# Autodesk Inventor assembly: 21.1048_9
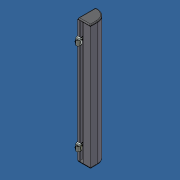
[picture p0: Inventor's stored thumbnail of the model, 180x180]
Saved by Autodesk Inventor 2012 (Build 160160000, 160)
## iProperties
Created: 2007-02
Part Number: 21.1048_9
Document SubType Name: Assembly
Designer: Andy Moles
Description: CLOSED PROT HANDLE FRONT MOUNT
Author: Andy Moles
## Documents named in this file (6)
- C:\Andys Backup Data\ANDY'S INVENTOR\INVENTOR LIBRARIES\PARTS LIBRARY\HANDLES LOCKS STOPS\21.1048_9 CLOSED PROT HANDLE FRONT.iam
- C:\Andys Backup Data\ANDY'S INVENTOR\INVENTOR LIBRARIES\PARTS LIBRARY\END CAPS\22.1054 END CAP FOR HANDLE PROFILE RIGHT GRAY.ipt
- C:\Andys Backup Data\ANDY'S INVENTOR\INVENTOR LIBRARIES\PARTS LIBRARY\END CAPS\22.1055 END CAP FOR HANDLE PROFILE LEFT GRAY.ipt
- C:\Andys Backup Data\ANDY'S INVENTOR\INVENTOR LIBRARIES\PARTS LIBRARY\HANDLES LOCKS STOPS\SUBCOMPONENTS\21.1048_8 HANDLE PROFILE.ipt
- C:\Andys Backup Data\ANDY'S INVENTOR\INVENTOR LIBRARIES\PARTS LIBRARY\FASTENING ELEMENTS\BUTTON HEAD FLANGE SCREWS\21.9966 M6X25 BUTTON HEAD FLANGE.ipt
- C:\Andys Backup Data\ANDY'S INVENTOR\INVENTOR LIBRARIES\PARTS LIBRARY\FASTENING ELEMENTS\NUTS\21.1330_2 M6 SQUARE NUT POS FXG.ipt
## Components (7 placed, 5 different names)
1. 21.1048_8 HANDLE PROFILE:1 — Flush:1, Mate:1, Flush:2, Mate:2, Mate:3, Flush:3, Mate:4, Mate:5, Flush:4, Insert:1, Insert:2, Mate:7, Mate:9, Angle:2
2. 22.1054 END CAP FOR HANDLE PROFILE RIGHT GRAY:1 — Mate:2, Mate:3, Flush:3, Angle:1
3. 22.1055 END CAP FOR HANDLE PROFILE LEFT GRAY:1 — Mate:4, Mate:5, Flush:4
4. 21.9966 M6X25 BUTTON HEAD FLANGE:1 — Insert:1, Mate:6
5. 21.9966 M6X25 BUTTON HEAD FLANGE:2 — Insert:2, Mate:8
6. 21.1330_2 M6 SQUARE NUT POS FXG:1 — Mate:6, Mate:7, Angle:1
7. 21.1330_2 M6 SQUARE NUT POS FXG:2 — Mate:8, Mate:9, Angle:2
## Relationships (17: Mate 9, Flush 4, Insert 2, Angle 2)
- Flush:1: 21.1048_8 HANDLE PROFILE:1
- Mate:1: 21.1048_8 HANDLE PROFILE:1
- Flush:2: 21.1048_8 HANDLE PROFILE:1
- Mate:2: 21.1048_8 HANDLE PROFILE:1 ↔ 22.1054 END CAP FOR HANDLE PROFILE RIGHT GRAY:1
- Mate:3: 21.1048_8 HANDLE PROFILE:1 ↔ 22.1054 END CAP FOR HANDLE PROFILE RIGHT GRAY:1
- Flush:3: 21.1048_8 HANDLE PROFILE:1 ↔ 22.1054 END CAP FOR HANDLE PROFILE RIGHT GRAY:1
- Mate:4: 21.1048_8 HANDLE PROFILE:1 ↔ 22.1055 END CAP FOR HANDLE PROFILE LEFT GRAY:1
- Mate:5: 21.1048_8 HANDLE PROFILE:1 ↔ 22.1055 END CAP FOR HANDLE PROFILE LEFT GRAY:1
- Flush:4: 21.1048_8 HANDLE PROFILE:1 ↔ 22.1055 END CAP FOR HANDLE PROFILE LEFT GRAY:1
- Insert:1: 21.1048_8 HANDLE PROFILE:1 ↔ 21.9966 M6X25 BUTTON HEAD FLANGE:1
- Insert:2: 21.1048_8 HANDLE PROFILE:1 ↔ 21.9966 M6X25 BUTTON HEAD FLANGE:2
- Mate:6: 21.9966 M6X25 BUTTON HEAD FLANGE:1 ↔ 21.1330_2 M6 SQUARE NUT POS FXG:1
- Mate:7: 21.1048_8 HANDLE PROFILE:1 ↔ 21.1330_2 M6 SQUARE NUT POS FXG:1
- Angle:1: 22.1054 END CAP FOR HANDLE PROFILE RIGHT GRAY:1 ↔ 21.1330_2 M6 SQUARE NUT POS FXG:1
- Mate:8: 21.9966 M6X25 BUTTON HEAD FLANGE:2 ↔ 21.1330_2 M6 SQUARE NUT POS FXG:2
- Mate:9: 21.1048_8 HANDLE PROFILE:1 ↔ 21.1330_2 M6 SQUARE NUT POS FXG:2
- Angle:2: 21.1048_8 HANDLE PROFILE:1 ↔ 21.1330_2 M6 SQUARE NUT POS FXG:2
